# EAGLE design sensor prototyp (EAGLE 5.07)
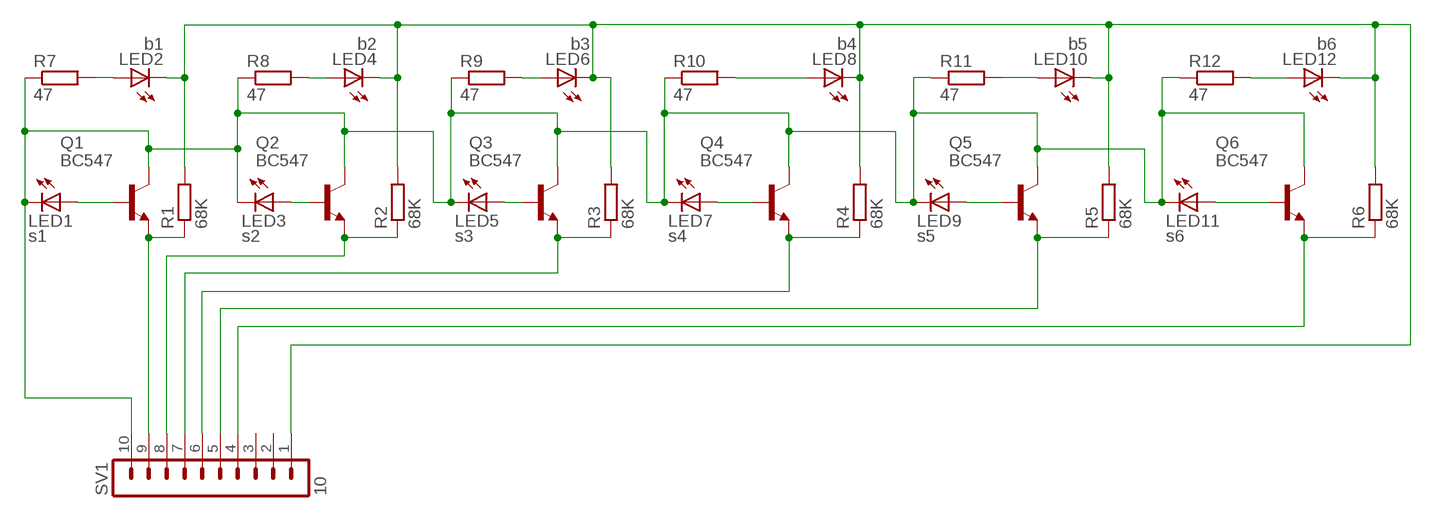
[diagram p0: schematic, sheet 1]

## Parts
LED1  s1  LED5MM  [LED5MM]
LED2  b1  LED5MM  [LED5MM]
LED3  s2  LED5MM  [LED5MM]
LED4  b2  LED5MM  [LED5MM]
LED5  s3  LED5MM  [LED5MM]
LED6  b3  LED5MM  [LED5MM]
LED7  s4  LED5MM  [LED5MM]
LED8  b4  LED5MM  [LED5MM]
LED9  s5  LED5MM  [LED5MM]
LED10  b5  LED5MM  [LED5MM]
LED11  s6  LED5MM  [LED5MM]
LED12  b6  LED5MM  [LED5MM]
Q1  BC547  [TO92]
Q2  BC547  [TO92]
Q3  BC547  [TO92]
Q4  BC547  [TO92]
Q5  BC547  [TO92]
Q6  BC547  [TO92]
R1  68K  R-EU_0204/7  [0204/7]
R2  68K  R-EU_0204/7  [0204/7]
R3  68K  R-EU_0204/7  [0204/7]
R4  68K  R-EU_0204/7  [0204/7]
R5  68K  R-EU_0204/7  [0204/7]
R6  68K  R-EU_0204/7  [0204/7]
R7  47  R-EU_0204/7  [0204/7]
R8  47  R-EU_0204/7  [0204/7]
R9  47  R-EU_0204/7  [0204/7]
R10  47  R-EU_0204/7  [0204/7]
R11  47  R-EU_0204/7  [0204/7]
R12  47  R-EU_0204/7  [0204/7]
SV1  10  MA10-1  [MA10-1]

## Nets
GRO: LED2.K(C) LED4.K(C) LED6.K(C) LED8.K(C) LED10.K(C) LED12.K(C) R1.2 R2.2 R3.2 R4.2 R5.2 R6.2 SV1.1
N$1: LED2.A R7.2
N$2: LED1.A Q1.2(B)
N$3: Q1.1(E) R1.1 SV1.9
N$4: LED4.A R8.2
N$5: LED8.A R10.2
N$6: LED3.A Q2.2(B)
N$7: Q2.1(E) R2.1 SV1.8
N$8: LED6.A R9.2
N$9: LED10.A R11.2
N$10: Q3.1(E) R3.1 SV1.7
N$11: LED5.A Q3.2(B)
N$12: LED12.A R12.2
N$14: LED9.A Q5.2(B)
N$17: Q5.1(E) R5.1 SV1.5
N$18: LED7.A Q4.2(B)
N$21: Q4.1(E) R4.1 SV1.6
N$23: LED11.A Q6.2(B)
N$24: Q6.1(E) R6.1 SV1.4
VCC: LED1.K(C) LED3.K(C) LED5.K(C) LED7.K(C) LED9.K(C) LED11.K(C) Q1.3(C) Q2.3(C) Q3.3(C) Q4.3(C) Q5.3(C) Q6.3(C) R7.1 R8.1 R9.1 R10.1 R11.1 R12.1 SV1.10
Unconnected: SV1.2 SV1.3

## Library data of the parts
LED1-LED12 = led:LED: LED
Q1-Q6 = transistor-npn:BC547*: NPN Transistor
R1-R12 = rcl:R-EU_: RESISTOR, European symbol
SV1 = con-lstb:MA10-1: PIN HEADER

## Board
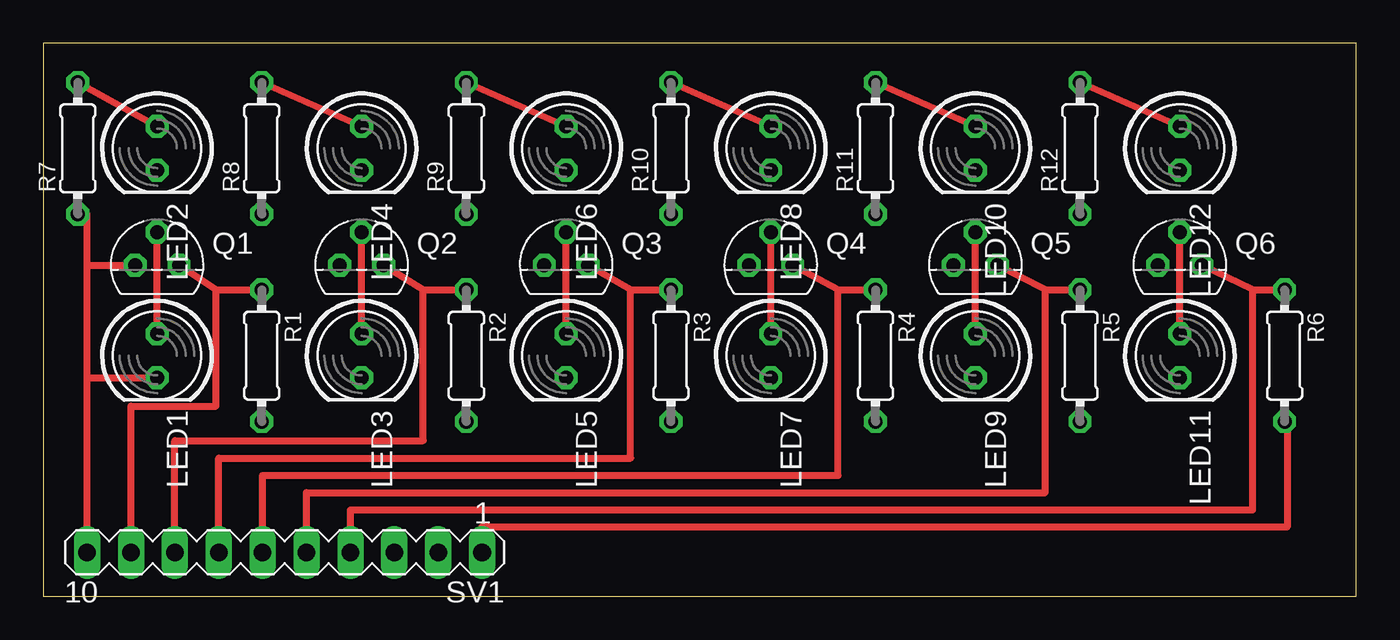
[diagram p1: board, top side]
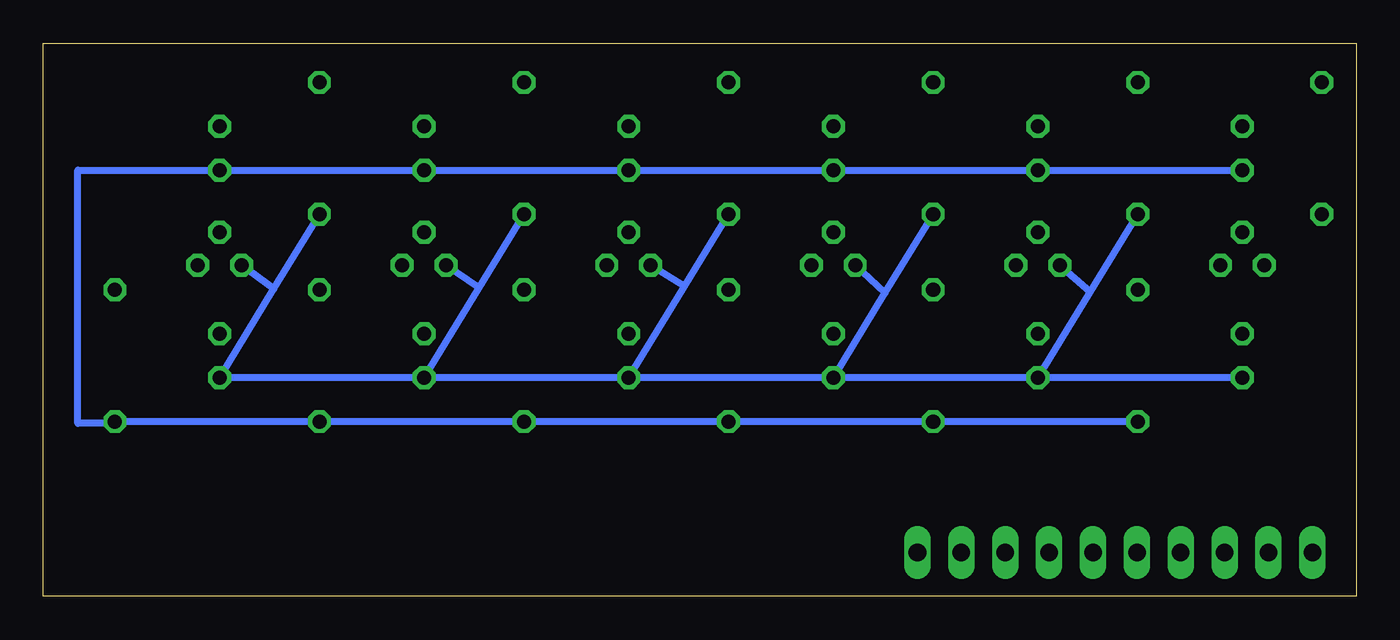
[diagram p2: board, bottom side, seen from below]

Size 76 x 32 mm. Coordinates in mm from the lower left corner, seen from the top.
Outline: 0,0 76,0 76,32 0,32 0,0
Copper layers (1*16): Top 0.035mm / dielectric 1.5mm / Bottom 0.035mm
Design rules "default": minimum track width 10mil, minimum drill 24mil, track to track 8mil, track to pad 8mil, pad to pad 8mil, via to via 8mil, smd to smd 8mil, copper to edge 40mil, drill to drill 8mil, minimum pad ring 10mil, minimum via ring 8mil, stop-mask expansion 4mil, vias tented up to drill 0mil, thermal gap 10mil

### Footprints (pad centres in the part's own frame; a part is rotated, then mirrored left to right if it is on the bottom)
LED5MM = drill 0.813 octagon: A -1.27,0; K 1.27,0
TO92 = drill 0.813 octagon: 1 1.27,0; 2 0,1.905; 3 -1.27,0
0204/7 = drill 0.813 octagon: 1 -3.81,0; 2 3.81,0
MA10-1 = drill 1.016 long: 1 -11.43,0; 2 -8.89,0; 3 -6.35,0; 4 -3.81,0; 5 -1.27,0; 6 1.27,0; 7 3.81,0; 8 6.35,0; 9 8.89,0; 10 11.43,0

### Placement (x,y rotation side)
LED1  6.59,13.92 270 top
LED2  6.59,25.92 270 top
LED3  18.43,13.92 270 top
LED4  18.43,25.92 270 top
LED5  30.27,13.92 270 top
LED6  30.27,25.92 270 top
LED7  42.11,13.92 270 top
LED8  42.11,25.92 270 top
LED9  53.95,13.92 270 top
LED10  53.95,25.92 270 top
LED11  65.79,13.92 270 top
LED12  65.79,25.92 270 top
Q1  6.59,19.16 0 top
Q2  18.43,19.16 0 top
Q3  30.27,19.16 0 top
Q4  42.11,19.16 0 top
Q5  53.95,19.16 0 top
Q6  65.79,19.16 0 top
R1  12.65,13.92 270 top
R2  24.49,13.92 270 top
R3  36.33,13.92 270 top
R4  48.17,13.92 270 top
R5  60.01,13.92 270 top
R6  71.85,13.92 270 top
R7  2,25.92 90 top
R8  12.65,25.92 90 top
R9  24.49,25.92 90 top
R10  36.33,25.92 90 top
R11  48.17,25.92 90 top
R12  60.01,25.92 90 top
SV1  13.97,2.54 180 top

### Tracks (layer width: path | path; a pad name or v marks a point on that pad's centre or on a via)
GRO
  Top 0.406: R6.2 72,10.11 72,4 25.4,4 SV1.1
  Bottom 0.406: R1.2 R2.2 R3.2 R4.2 R5.2 R6.2 71.85,10 74,10 74,24.65 LED12.K LED10.K LED8.K LED6.K LED4.K LED2.K
N$1
  Top 0.406: R7.2 LED2.A
N$2
  Top 0.406: LED1.A Q1.2
N$3
  Top 0.406: 10,17.73 R1.1 | 10,17.73 10,11 5.08,11 SV1.9 | 10,17.73 Q1.1
N$4
  Top 0.406: R8.2 LED4.A
N$5
  Top 0.406: R10.2 LED8.A
N$6
  Top 0.406: LED3.A Q2.2
N$7
  Top 0.406: 22,17.73 R2.1 | 22,17.73 22,9 7.62,9 SV1.8 | 22,17.73 Q2.1
N$8
  Top 0.406: R9.2 LED6.A
N$9
  Top 0.406: R11.2 LED10.A
N$10
  Top 0.406: 34,17.73 R3.1 | 34,17.73 34,8 10.16,8 SV1.7 | 34,17.73 Q3.1
N$11
  Top 0.406: LED5.A Q3.2
N$12
  Top 0.406: R12.2 LED12.A
N$14
  Top 0.406: LED9.A Q5.2
N$17
  Top 0.406: 58,17.73 R5.1 | 58,17.73 58,6 15.24,6 SV1.5 | 58,17.73 Q5.1
N$18
  Top 0.406: LED7.A Q4.2
N$21
  Top 0.406: 46,17.73 R4.1 | 46,17.73 46,7 12.7,7 SV1.6 | 46,17.73 Q4.1
N$23
  Top 0.406: LED11.A Q6.2
N$24
  Top 0.406: 70,17.73 R6.1 | 70,17.73 70,5 17.78,5 SV1.4 | 70,17.73 Q6.1
VCC
  Top 0.406: R7.1 2.54,22.11 2.54,19.16 | SV1.10 2.54,12.65 | 2.54,12.65 LED1.K | 2.54,19.16 Q1.3 | 2.54,12.65 2.54,19.16
  Bottom 0.406: LED1.K LED3.K | LED3.K LED5.K | LED5.K LED7.K | LED7.K LED9.K | LED3.K 15.39,17.63 | 15.39,17.63 R8.1 | 15.39,17.63 Q2.3 | LED5.K 27.27,17.56 | 27.27,17.56 R9.1 | 27.27,17.56 Q3.3 | LED7.K 39.6,16.76 38.88,17.93 | 38.88,17.93 R10.1 | LED9.K 50.77,17.86 | 50.77,17.86 R11.1 | 50.77,17.86 Q5.3 | LED9.K LED11.K 62.65,17.79 | 62.65,17.79 R12.1 | 62.65,17.79 Q6.3 | 38.88,17.93 Q4.3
